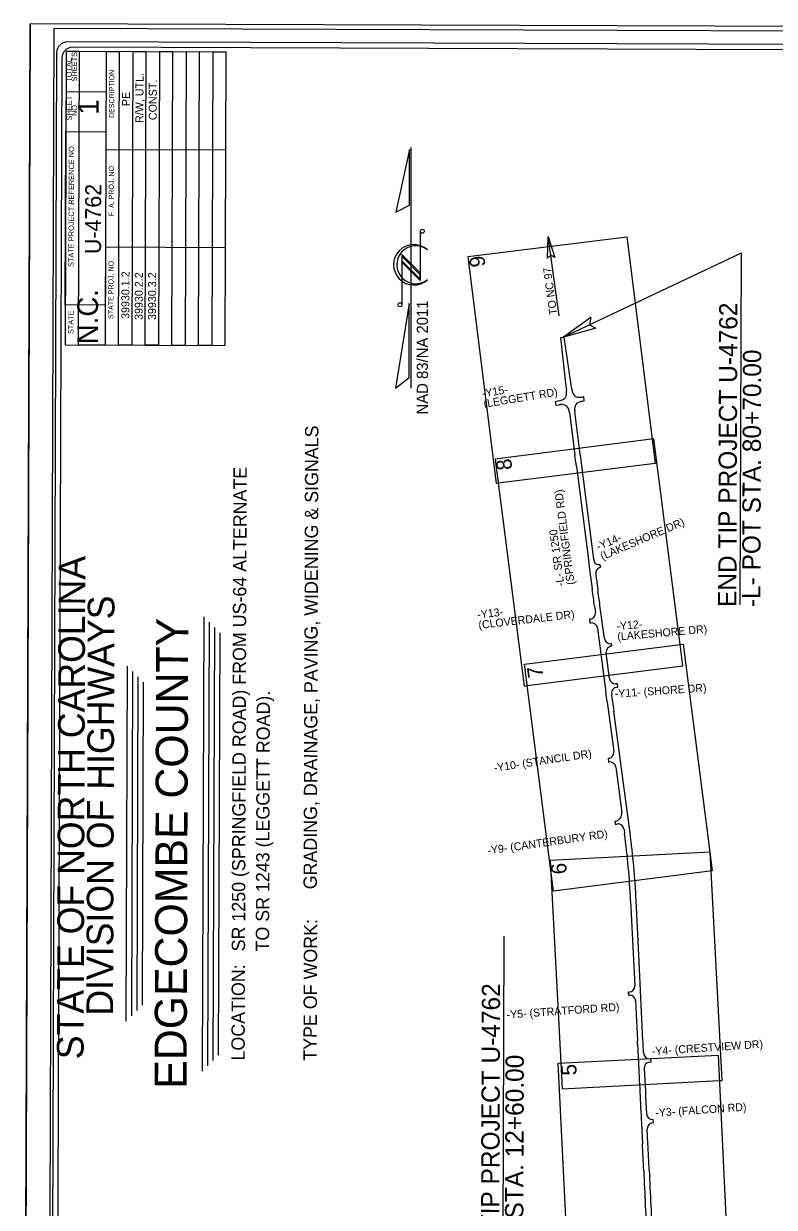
# Model space of a CAD drawing. Extents: x 2364794 to 2387902, y 795230 to 810426.
# Drawn here: x 2364794 to 2369718, y 802661 to 810426 of the extents above; entities that cross this region are included whole.
import ezdxf

# ---------------------------------------------------------------- set-up
doc = ezdxf.new("R2010")
doc.units = 0
for name, color, linetype in [('Mis Object Lines', 7, 'Continuous'), ('Old_Level_10', 7, 'Continuous'), ('Old_Level_15', 7, 'Continuous'), ('Old_Level_2', 7, 'Continuous'), ('Old_Level_21', 7, 'Continuous'), ('Old_Level_22', 7, 'Continuous'), ('Old_Level_4', 7, 'Continuous'), ('Old_Level_5', 7, 'Continuous'), ('Old_Level_7', 7, 'Continuous'), ('Plan Sheet CELL', 7, 'Continuous'), ('Sub End Bent Cap Lines CELL', 7, 'Continuous')]:
    doc.layers.add(name, color=color, linetype=linetype)

msp = doc.modelspace()

# ---------------------------------------------------------------- linework, layer by layer
at = {"layer": 'Mis Object Lines'}
for p, q in [((2365966.9, 803553.4), (2365977.5, 806535.4)), ((2366002, 803588.3), (2366012.4, 806500.3)), ((2366037.2, 803623.2), (2366047.2, 806465.2)), ((2366072.3, 803658.1), (2366082.1, 806430)), ((2365466.9, 803881.7), (2365475.1, 806211)), ((2365502, 803916.6), (2365510, 806175.9)), ((2365537.2, 803951.5), (2365544.8, 806140.7)), ((2365572.3, 803986.4), (2365579.7, 806105.6))]:
    msp.add_line(p, q, dxfattribs=at)
for points in [[(2372289.6, 810280.9), (2365079.8, 810306.4)], [(2370959.6, 810250.6), (2365114.6, 810271.2)], [(2365009.5, 810236.7), (2364972.8, 799876.6)], [(2365044.4, 810201.5), (2365009.3, 800261.6)], [(2366115.6, 808314.7), (2366122.4, 810239.7), (2366035, 810240), (2366028.1, 808315), (2365940.7, 808315.3), (2365947.5, 810240.3), (2365860, 810240.6), (2365853.2, 808315.7), (2365765.7, 808315.9), (2365772.5, 810240.9), (2365685, 810241.2), (2365678.2, 808316.2), (2365590.7, 808316.5), (2365597.5, 810241.5), (2365510, 810241.8), (2365503.2, 808316.8), (2365415.7, 808317.2), (2365422.5, 810242.1), (2365335, 810242.5), (2365328.2, 808317.5), (2365153.2, 808318.1), (2365160, 810243.1), (2365072.5, 810243.4), (2365065.7, 808318.4), (2366115.6, 808314.7), (2366118, 808956.2), (2365330.5, 808959), (2365329.2, 808580), (2365066.6, 808580.9), (2365070.7, 809718.5), (2365333.1, 809717.5), (2365332.7, 809600.6), (2366120.2, 809597.8), (2366122.4, 810239.7), (2365072.5, 810243.4), (2365071.5, 809980.9), (2365334, 809980)]]:
    msp.add_lwpolyline(points, dxfattribs=at)
for centre in [(2365079.1, 810236.4), (2365114, 810201.3)]:
    msp.add_arc(centre, 70, 89.79762, 179.79762, dxfattribs=at)
at = {"layer": 'Old_Level_10'}
for points in [[(2368230, 808887.1), (2368234.9, 809029.5), (2368278.8, 808893), (2368251.6, 808907.4)], [(2368547.3, 808428.2), (2368327.4, 808366.8), (2368514.7, 808499.9), (2368505.9, 808451.4)]]:
    msp.add_lwpolyline(points, close=True, dxfattribs=at)
at = {"layer": 'Old_Level_15'}
for p, q in [((2368306.2, 808509.8), (2368234.9, 809029.5)), ((2368327.4, 808366.8), (2369502.3, 808923.5)), ((2369494.2, 806614.5), (2369502.3, 808923.5)), ((2367937.1, 801904.7), (2367946.1, 804439.4))]:
    msp.add_line(p, q, dxfattribs=at)
at = {"layer": 'Old_Level_2'}
for p, q in [((2366251.4, 805894.6), (2366251.4, 805894.6)), ((2365867.9, 805055.6), (2365867.9, 805055.6))]:
    msp.add_line(p, q, dxfattribs=at)
at = {"layer": 'Old_Level_21'}
msp.add_lwpolyline([(2364835.2, 810426.2), (2364793.5, 798638.3), (2372493.4, 798611.1), (2372535.1, 810399)], close=True, dxfattribs=at)
at = {"layer": 'Old_Level_22'}
msp.add_lwpolyline([(2372336.7, 798702.6), (2372377.9, 810368.1), (2364992.2, 810394.2), (2364951, 798728.7)], close=True, dxfattribs=at)
at = {"layer": 'Old_Level_4'}
for p, q in [((2367336, 808034.9), (2367336, 809614.4)), ((2367395.5, 809064.7), (2367395.5, 808740.6)), ((2367440.3, 808944), (2367442, 808942.7)), ((2367395.5, 808791.1), (2367274.8, 808911.9)), ((2367274.8, 808911.9), (2367274.8, 808582.4)), ((2367395.5, 808779.2), (2367274.8, 808900)), ((2367274.8, 808900), (2367274.8, 808870.3)), ((2367395.5, 808749.6), (2367274.8, 808870.3)), ((2367274.8, 808870.3), (2367395.5, 808749.6)), ((2367395.5, 808740.6), (2367274.8, 808861.3)), ((2367395.5, 808749.6), (2367395.5, 808779.2))]:
    msp.add_line(p, q, dxfattribs=at)
for points in [[(2367325.1, 809600.5), (2367234.9, 809190.4), (2367325.1, 809236)], [(2367323.1, 808591.4), (2367233.7, 808034.9), (2367323.1, 808105.4)]]:
    msp.add_lwpolyline(points, close=True, dxfattribs=at)
for centre in [(2367408.4, 809064.5), (2367261.9, 808581.9)]:
    msp.add_circle(centre, 12.9, dxfattribs=at)
for centre, radius, start, end in [((2367352.8, 808844.4), 132.7, 47.84002, 312.39406), ((2367365.6, 808844.5), 124.4, 53.09504, 308.62871)]:
    msp.add_arc(centre, radius, start, end, dxfattribs=at)
at = {"layer": 'Old_Level_5'}
for p, q in [((2368328.2, 808367.4), (2368315.6, 808365.7)), ((2368315.6, 808365.7), (2368348.2, 808067.4)), ((2368339.4, 808368.8), (2368330.3, 808367.6)), ((2368383.9, 808072.1), (2368339.4, 808368.8)), ((2368348.2, 808067.4), (2368354.4, 808019.9)), ((2368389.7, 808027.7), (2368383.9, 808072.1)), ((2368306.7, 807952), (2368279.7, 807946.1)), ((2368279.7, 807946.1), (2368283.4, 807923.6)), ((2368283.4, 807923.6), (2368306.9, 807926.3)), ((2368318.2, 807927.6), (2368322.6, 807928.2)), ((2368451.1, 807947.7), (2368451.7, 807947.8)), ((2368467.2, 807977.1), (2368456.1, 807975.8)), ((2368457.9, 807949), (2368471.3, 807951.5)), ((2368471.3, 807951.5), (2368467.2, 807977.1)), ((2368373.4, 807874.5), (2368409.4, 807597.6)), ((2368445.1, 807602.2), (2368408.8, 807881.4)), ((2368419.2, 807521.7), (2368497.9, 806908.3)), ((2368533.6, 806912.8), (2368454.9, 807526.3)), ((2368572.3, 806858.4), (2368578.8, 806860.7)), ((2368578.8, 806860.7), (2368573, 806879)), ((2368602.8, 806391.7), (2368574, 806609.9)), ((2368538.3, 806605.2), (2368543.7, 806564.1)), ((2368508.9, 806519.1), (2368505.3, 806518.7)), ((2368505.3, 806518.7), (2368508.1, 806494.3)), ((2368508.1, 806494.3), (2368513.6, 806494.9)), ((2368557.4, 806460.3), (2368613.3, 806037.4)), ((2368637.4, 806129.7), (2368615.2, 806297.9)), ((2368650, 806357.5), (2368646.3, 806357.1)), ((2368651.1, 806343), (2368650, 806357.5)), ((2368690, 806095), (2368677.1, 806094.9)), ((2368686.9, 806073.5), (2368691.4, 806073.9)), ((2368691.4, 806073.9), (2368690, 806095)), ((2368629.5, 805912.1), (2368664.1, 805650.4)), ((2368756.1, 805230.2), (2368665.2, 805916.9)), ((2368629.3, 805605.4), (2368626.9, 805605.1)), ((2368626.9, 805605.1), (2368629.8, 805582.2)), ((2368629.8, 805582.2), (2368633.3, 805582.6)), ((2368677.7, 805548.1), (2368717, 805251)), ((2368771, 805117.7), (2368756.1, 805230.2)), ((2368674, 805194.9), (2368671.9, 805194.6)), ((2368671.9, 805194.6), (2368674.3, 805174.1)), ((2368674.3, 805174.1), (2368687.7, 805175.5)), ((2368731.6, 805141), (2368735.3, 805113)), ((2368775.2, 804671.9), (2368802.5, 804113.9)), ((2368830.8, 804270.9), (2368811.2, 804673.7)), ((2368856, 803755.6), (2368830.8, 804270.9)), ((2368765, 804072), (2368759, 804071.7)), ((2368759, 804071.7), (2368760.2, 804052.7)), ((2368760.2, 804052.7), (2368764.2, 804053)), ((2368807.3, 804015.1), (2368820.1, 803753.8)), ((2368820.9, 803734.3), (2368824.8, 803643)), ((2368859.5, 803673.5), (2368856.9, 803735.8)), ((2368898.4, 803613.3), (2368908.2, 803614.7)), ((2368906.6, 803635.4), (2368900.7, 803635.2)), ((2368908, 803635.5), (2368906.6, 803635.4)), ((2368909.4, 803614.8), (2368908, 803635.5)), ((2368908.2, 803614.7), (2368909.4, 803614.8)), ((2368846, 803213.3), (2368852.7, 803078.2)), ((2368922.7, 803236.1), (2368920.4, 803236)), ((2368921.8, 803214.5), (2368924.2, 803214.6)), ((2368924.2, 803214.6), (2368922.7, 803236.1)), ((2368888.7, 803080), (2368884.1, 803172.6))]:
    msp.add_line(p, q, dxfattribs=at)
msp.add_lwpolyline([(2368330.3, 808367.6), (2368327.4, 808366.8), (2368328.2, 808367.4)], dxfattribs=at)
for centre, radius, start, end in [((2368235.4, 808004.4), 120, 354.57947, 7.41804), ((2368508.7, 808043.2), 120, 187.41804, 200.2566), ((2368281.1, 808069.3), 120, 282.32916, 295.16773), ((2368320.9, 807807.1), 120, 83.87456, 96.71313), ((2368315.1, 807996.9), 40, 295.16773, 354.57947), ((2368329.4, 807886.7), 40, 20.2566, 83.87456), ((2368433.7, 808015.5), 40, 200.2566, 263.72834), ((2368448.1, 807904.4), 40, 113.43497, 174.57947), ((2368442.4, 808095), 120, 263.72834, 276.56691), ((2368479.9, 807831), 120, 100.5964, 113.43497), ((2368254.4, 807859), 120, 7.41804, 20.2566), ((2368527.8, 807896.9), 120, 174.57947, 187.41804), ((2328762, 802435.6), 39982, 7.30844, 7.41804), ((2328762, 802435.6), 40018, 7.30844, 7.41804), ((2391111.5, 809808.5), 22798.9, 187.30844, 187.80171), ((2391111.5, 809808.5), 22762.9, 187.30844, 187.33097), ((2368564.5, 806907.8), 30, 187.33097, 286.50472), ((2368586, 806820.8), 40, 109.98662, 187.55549), ((2391111.5, 809808.5), 22762.9, 187.55549, 187.80171), ((2345971.6, 803623.7), 22762.8, 7.52626, 7.80171), ((2345971.6, 803623.7), 22798.9, 7.52626, 7.80171), ((2368504.1, 806558.8), 40, 276.89921, 7.52626), ((2368517.8, 806455.1), 40, 7.52626, 96.0115), ((2368642.5, 806397), 40, 187.52626, 275.45413), ((2368654.9, 806303.2), 40, 95.47906, 187.52626), ((2368677.1, 806134.9), 40, 187.52626, 269.99737), ((2368690.5, 806033.6), 40, 95.11218, 187.44758), ((2358717.3, 804729.9), 9982, 7.17269, 7.52626), ((2358717.3, 804729.9), 10018, 7.17269, 7.44758), ((2378560.8, 807227.1), 10018, 187.17267, 187.5424), ((2378560.8, 807227.1), 9982, 187.17267, 187.5424), ((2368624.5, 805645.1), 40, 276.95488, 7.54241), ((2368638, 805542.9), 40, 7.54241, 96.80232), ((2368667.5, 805244.5), 50, 277.50895, 7.54241), ((2368691.9, 805135.8), 40, 7.54241, 96.14887), ((2363433, 804411), 5348.6, 2.79654, 7.54241), ((2363433, 804411), 5384.6, 2.79654, 7.54241), ((2368767.3, 804013.1), 40, 2.79655, 94.52994), ((2368762.5, 804112), 40, 273.54347, 2.79655), ((2365928.4, 803612.6), 2895.1, 2.40884, 2.79656), ((2365928.4, 803612.6), 2931.1, 2.40884, 2.79656), ((2368899.5, 803675.2), 40, 182.40885, 271.66887), ((2372339.7, 803790.9), 3518, 182.40885, 182.79745), ((2677047.3, 818679.9), 308589.2, 182.797446, 182.872893), ((2368904.2, 803573.7), 40, 98.30308, 182.80659), ((2677047.3, 818679.9), 308553.2, 182.806587, 182.861944), ((2368918.9, 803276), 40, 182.86194, 272.16607), ((2368924, 803174.6), 40, 93.13958, 182.87289), ((2343687.4, 801815.3), 25197.1, 2.47241, 2.87289), ((2343687.4, 801815.3), 25233.1, 2.47241, 2.87289), ((2425310.1, 805339.7), 56501.7, 182.47241, 182.94048), ((2425310.1, 805339.7), 56465.7, 182.47241, 182.94048)]:
    msp.add_arc(centre, radius, start, end, dxfattribs=at)
at = {"layer": 'Old_Level_7'}
for points in [[(2367905.9, 807411.1), (2367894.5, 807409.7), (2367708.9, 808898.3), (2368750.8, 809028.2), (2368916.4, 807700.4)], [(2369099.5, 806353.6), (2368927.3, 807701.8), (2367885.7, 807568.7), (2368075.8, 806080.8), (2368096.1, 806083.4)], [(2368916.4, 807700.4), (2368936.4, 807539.7)], [(2368936.4, 807539.7), (2367905.9, 807411.1)], [(2368251, 804870.8), (2368078.3, 806223.1), (2369119.8, 806356.1), (2369294.2, 804991)], [(2368096.1, 806083.4), (2369117.3, 806213.9), (2369099.5, 806353.6)], [(2369356.8, 803492.2), (2369374.6, 803493.2), (2369296.1, 804991.1), (2368247.6, 804936.2), (2368317.1, 803608.1)], [(2369294.2, 804991), (2369309.9, 804868.2), (2368268.3, 804735.2), (2368251, 804870.8)], [(2368394, 802110), (2368373.1, 802109), (2368300, 803607.2), (2369348.7, 803658.4), (2369413.8, 802325.9)], [(2368317.1, 803608.1), (2368326, 803438.3), (2369356.8, 803492.2)]]:
    msp.add_lwpolyline(points, dxfattribs=at)
at = {"layer": 'Plan Sheet CELL'}
msp.add_line((2364793.5, 798638.3), (2364835.2, 810426.2), dxfattribs=at)

# ---------------------------------------------------------------- texts
at = {"layer": 'Mis Object Lines'}
for s, height, p in [('TOTAL', 35, (2365107.8, 810044.8)), ('SHEETS', 35, (2365142.8, 810047)), ('DESCRIPTION', 33.6, (2365387.1, 809807.2)), ('SHEET', 35, (2365109.4, 809791.4)), ('NO.', 35, (2365144.1, 809820.3)), ('1', 135.4, (2365285.5, 809828.6)), ('STATE PROJECT REFERENCE NO.', 34.999, (2365121.8, 808829.9)), ('F. A. PROJ. NO.', 33.6, (2365384.7, 809162.5)), ('STATE PROJ. NO.', 33.6, (2365382.3, 808488.4)), ('N.C.', 135.45, (2365280.2, 808322.9)), ('STATE', 35, (2365120.2, 808389.9)), ('STATE OF NORTH CAROLINA', 174.999, (2365186.4, 803632.1)), ('DIVISION OF HIGHWAYS', 174.999, (2365379.8, 803917.8)), ('TYPE OF WORK:', 87.501, (2366715.9, 803622.2)), ('LOCATION: ', 87.5, (2366243.3, 803623.9))]:
    msp.add_text(s, height=height, rotation=89.79762, dxfattribs=at).set_placement(p)
at = {"layer": 'Old_Level_15'}
for s, height, rotation, p in [('9', 100, 97.10765, (2367823.3, 808834.9)), ('TO NC 97', 52, 97.75532, (2368294, 808519.5)), ('END TIP PROJECT U-4762', 120, 89.79762, (2369468.8, 806598.7)), ('-L- POT STA. 80+70.00', 120, 89.79762, (2369626.1, 806598.2)), ('-Y15- ', 52, 9.36434, (2367804.2, 807974.1)), ('(LEGGETT RD)', 52, 9.36434, (2367815.3, 807906.8)), ('8', 100, 97.27972, (2367999.3, 807503.2)), ('(SPRINGFIELD RD)', 52, 97.41804, (2368407.9, 806748)), ('(LAKESHORE DR)', 52, 23.05916, (2368590.2, 806906.3)), ('-L- SR 1250 ', 52, 97.41804, (2368340.3, 806739.2)), ('-Y14- ', 52, 23.05916, (2368563.5, 806969)), ('-Y13- ', 52, 6.5768, (2367772.1, 806522.9)), ('(CLOVERDALE DR)', 52, 6.5768, (2367779.9, 806455.2)), ('-Y12- ', 52, 4.98798, (2368684.2, 806447.1)), ('(LAKESHORE DR)', 52, 4.98798, (2368690.1, 806379.2)), ('7', 100, 97.27835, (2368203, 806141.3)), ('-Y11- (SHORE DR)', 52, 3.89042, (2368672.9, 806004.2)), ('-Y10- (STANCIL DR)', 52, 8.52634, (2367880.6, 805517.6)), ('-Y9- (CANTERBURY RD)', 52, 8.14112, (2367839.9, 804975.1)), ('6', 100, 92.99787, (2368355.8, 804848)), ('BEGIN TIP PROJECT U-4762', 120, 89.79762, (2367911.6, 801972.3)), ('-Y5- (STRATFORD RD)', 52, 4.04438, (2367963.3, 803898.6)), ('-Y4- (CRESTVIEW DR)', 52, 3.78773, (2368916, 803658.9)), ('-L- POT STA. 12+60.00', 120, 89.79762, (2368068.9, 801971.7)), ('5', 100, 92.79428, (2368421.4, 803528.2)), ('-Y3- (FALCON RD)', 52, 3.8206, (2368938.7, 803255))]:
    msp.add_text(s, height=height, rotation=rotation, dxfattribs=at).set_placement(p)
at = {"layer": 'Old_Level_4'}
msp.add_text('NAD 83/NA 2011   ', height=72.9, rotation=90, dxfattribs=at).set_placement((2367445.2, 807862.3))
at = {"layer": 'Sub End Bent Cap Lines CELL'}
for s, height, p in [('R/W, UTL.', 52.5, (2365578.7, 809774.8)), ('CONST.', 52.5, (2365666.2, 809793.3)), ('PE', 52.5, (2365490.9, 809885)), ('U-4762', 105, (2365300.9, 808914.5)), ('39930.1.2', 52.5, (2365486.7, 808489)), ('39930.2.2', 52.5, (2365574.2, 808482.4)), ('39930.3.2', 52.5, (2365661.6, 808482.1)), (' GRADING, DRAINAGE, PAVING, WIDENING & SIGNALS', 87.501, (2366716.4, 804714.6)), ('SR 1250 (SPRINGFIELD ROAD) FROM US-64 ALTERNATE', 87.501, (2366245.8, 804339.8)), ('EDGECOMBE COUNTY', 210, (2365862.2, 803438.4)), ('TO SR 1243 (LEGGETT ROAD).', 87.501, (2366403.3, 804339.2))]:
    msp.add_text(s, height=height, rotation=89.79762, dxfattribs=at).set_placement(p)

doc.saveas('drawing.dxf')
